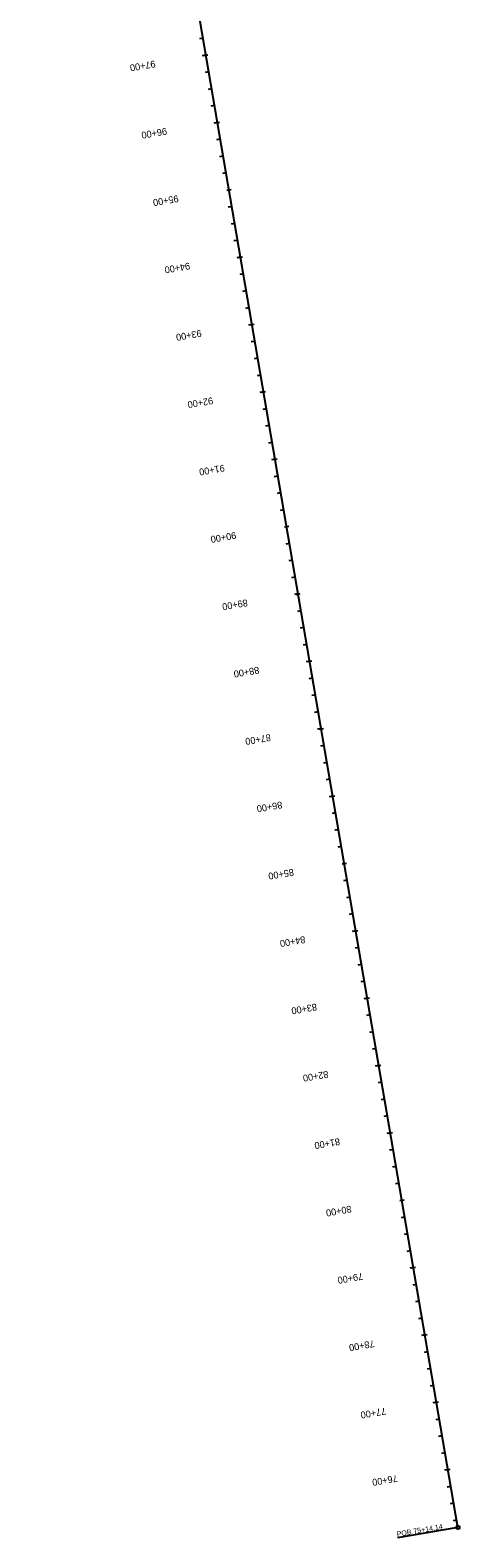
# Model space of a CAD drawing. Extents: x 11526371 to 11527168, y 9590726 to 9599509.
# Drawn here: x 11526540 to 11527168, y 9590726 to 9592932 of the extents above; entities that cross this region are included whole.
import ezdxf

# ---------------------------------------------------------------- set-up
doc = ezdxf.new("R2010")
doc.units = 0
for name, color, linetype in [('Alignment', 7, 'Continuous'), ('TextAlignment', 7, 'Continuous'), ('TextAlignmentLrg', 7, 'Continuous'), ('TextAlignmentSml', 7, 'Continuous')]:
    doc.layers.add(name, color=color, linetype=linetype)

msp = doc.modelspace()

# ---------------------------------------------------------------- linework, layer by layer
at = {"layer": 'Alignment'}
msp.add_line((11527165.7, 9590741), (11526539.8, 9594397.6), dxfattribs=at)
at = {"layer": 'TextAlignment'}
for p in [(11527165.7, 9590741), (11527077, 9590725.8)]:
    msp.add_line(p, (11527077, 9590725.8), dxfattribs=at)
msp.add_circle((11527165.7, 9590741), 2.67, dxfattribs=at)
at = {"layer": 'TextAlignmentLrg'}
for p, q in [((11526796.9, 9592895.5), (11526791.5, 9592894.6)), ((11526813.8, 9592796.9), (11526808.4, 9592796)), ((11526827.7, 9592697.8), (11526833.7, 9592698.9)), ((11526847.5, 9592599.8), (11526842.2, 9592598.9)), ((11526864.4, 9592501.2), (11526859, 9592500.3)), ((11526881.3, 9592402.7), (11526875.9, 9592401.7)), ((11526898.2, 9592304.1), (11526892.8, 9592303.2)), ((11526912, 9592205), (11526918, 9592206)), ((11526931.9, 9592107), (11526926.5, 9592106)), ((11526948.8, 9592008.4), (11526943.4, 9592007.5)), ((11526965.6, 9591909.8), (11526960.3, 9591908.9)), ((11526982.5, 9591811.3), (11526977.1, 9591810.3)), ((11526996.4, 9591712.2), (11527002.4, 9591713.2)), ((11527016.3, 9591614.1), (11527010.9, 9591613.2)), ((11527033.1, 9591515.6), (11527027.8, 9591514.6)), ((11527050, 9591417), (11527044.6, 9591416.1)), ((11527066.9, 9591318.4), (11527061.5, 9591317.5)), ((11527080.7, 9591219.3), (11527086.8, 9591220.4)), ((11527100.6, 9591121.3), (11527095.2, 9591120.4)), ((11527117.5, 9591022.7), (11527112.1, 9591021.8)), ((11527134.4, 9590924.2), (11527129, 9590923.2)), ((11527151.2, 9590825.6), (11527145.9, 9590824.7))]:
    msp.add_line(p, q, dxfattribs=at)
at = {"layer": 'TextAlignmentSml'}
for p, q in [((11526792.7, 9592920.1), (11526787.3, 9592919.2)), ((11526793.9, 9592895), (11526799.9, 9592896)), ((11526801.1, 9592870.9), (11526795.8, 9592869.9)), ((11526805.4, 9592846.2), (11526800, 9592845.3)), ((11526809.6, 9592821.6), (11526804.2, 9592820.6)), ((11526810.8, 9592796.4), (11526816.8, 9592797.4)), ((11526818, 9592772.3), (11526812.6, 9592771.4)), ((11526822.2, 9592747.6), (11526816.9, 9592746.7)), ((11526826.5, 9592723), (11526821.1, 9592722.1)), ((11526827.7, 9592697.8), (11526833.7, 9592698.9)), ((11526834.9, 9592673.7), (11526829.5, 9592672.8)), ((11526839.1, 9592649.1), (11526833.7, 9592648.2)), ((11526843.3, 9592624.4), (11526837.9, 9592623.5)), ((11526844.5, 9592599.3), (11526850.6, 9592600.3)), ((11526851.8, 9592575.2), (11526846.4, 9592574.2)), ((11526856, 9592550.5), (11526850.6, 9592549.6)), ((11526860.2, 9592525.9), (11526854.8, 9592524.9)), ((11526861.4, 9592500.7), (11526867.4, 9592501.7)), ((11526868.6, 9592476.6), (11526863.3, 9592475.7)), ((11526872.9, 9592451.9), (11526867.5, 9592451)), ((11526877.1, 9592427.3), (11526871.7, 9592426.4)), ((11526878.3, 9592402.1), (11526884.3, 9592403.2)), ((11526885.5, 9592378), (11526880.1, 9592377.1)), ((11526889.7, 9592353.4), (11526884.3, 9592352.5)), ((11526893.9, 9592328.7), (11526888.6, 9592327.8)), ((11526895.1, 9592303.6), (11526901.2, 9592304.6)), ((11526902.4, 9592279.5), (11526897, 9592278.5)), ((11526906.6, 9592254.8), (11526901.2, 9592253.9)), ((11526910.8, 9592230.2), (11526905.4, 9592229.2)), ((11526912, 9592205), (11526918, 9592206)), ((11526919.3, 9592180.9), (11526913.9, 9592180)), ((11526923.5, 9592156.2), (11526918.1, 9592155.3)), ((11526927.7, 9592131.6), (11526922.3, 9592130.7)), ((11526928.9, 9592106.4), (11526934.9, 9592107.5)), ((11526936.1, 9592082.3), (11526930.7, 9592081.4)), ((11526940.3, 9592057.7), (11526935, 9592056.8)), ((11526944.6, 9592033), (11526939.2, 9592032.1)), ((11526945.8, 9592007.9), (11526951.8, 9592008.9)), ((11526953, 9591983.8), (11526947.6, 9591982.8)), ((11526957.2, 9591959.1), (11526951.8, 9591958.2)), ((11526961.4, 9591934.5), (11526956, 9591933.5)), ((11526962.6, 9591909.3), (11526968.7, 9591910.3)), ((11526969.9, 9591885.2), (11526964.5, 9591884.3)), ((11526974.1, 9591860.5), (11526968.7, 9591859.6)), ((11526978.3, 9591835.9), (11526972.9, 9591835)), ((11526979.5, 9591810.7), (11526985.5, 9591811.8)), ((11526986.7, 9591786.6), (11526981.4, 9591785.7)), ((11526991, 9591762), (11526985.6, 9591761.1)), ((11526995.2, 9591737.3), (11526989.8, 9591736.4)), ((11526996.4, 9591712.2), (11527002.4, 9591713.2)), ((11527003.6, 9591688.1), (11526998.2, 9591687.1)), ((11527007.8, 9591663.4), (11527002.4, 9591662.5)), ((11527012, 9591638.8), (11527006.7, 9591637.8)), ((11527013.2, 9591613.6), (11527019.3, 9591614.6)), ((11527020.5, 9591589.5), (11527015.1, 9591588.6)), ((11527024.7, 9591564.8), (11527019.3, 9591563.9)), ((11527028.9, 9591540.2), (11527023.5, 9591539.3)), ((11527030.1, 9591515), (11527036.2, 9591516.1)), ((11527037.4, 9591490.9), (11527032, 9591490)), ((11527041.6, 9591466.3), (11527036.2, 9591465.4)), ((11527045.8, 9591441.6), (11527040.4, 9591440.7)), ((11527047, 9591416.5), (11527053, 9591417.5)), ((11527054.2, 9591392.4), (11527048.8, 9591391.4)), ((11527058.4, 9591367.7), (11527053.1, 9591366.8)), ((11527062.7, 9591343.1), (11527057.3, 9591342.1)), ((11527063.9, 9591317.9), (11527069.9, 9591318.9)), ((11527071.1, 9591293.8), (11527065.7, 9591292.9)), ((11527075.3, 9591269.1), (11527069.9, 9591268.2)), ((11527079.5, 9591244.5), (11527074.2, 9591243.6)), ((11527080.7, 9591219.3), (11527086.8, 9591220.4)), ((11527088, 9591195.2), (11527082.6, 9591194.3)), ((11527092.2, 9591170.6), (11527086.8, 9591169.7)), ((11527096.4, 9591145.9), (11527091, 9591145)), ((11527097.6, 9591120.8), (11527103.6, 9591121.8)), ((11527104.8, 9591096.7), (11527099.5, 9591095.7)), ((11527109.1, 9591072), (11527103.7, 9591071.1)), ((11527113.3, 9591047.4), (11527107.9, 9591046.5)), ((11527114.5, 9591022.2), (11527120.5, 9591023.2)), ((11527121.7, 9590998.1), (11527116.3, 9590997.2)), ((11527125.9, 9590973.4), (11527120.5, 9590972.5)), ((11527130.1, 9590948.8), (11527124.8, 9590947.9)), ((11527131.3, 9590923.6), (11527137.4, 9590924.7)), ((11527138.6, 9590899.5), (11527133.2, 9590898.6)), ((11527142.8, 9590874.9), (11527137.4, 9590874)), ((11527147, 9590850.2), (11527141.6, 9590849.3)), ((11527148.2, 9590825.1), (11527154.3, 9590826.1)), ((11527155.5, 9590801), (11527150.1, 9590800)), ((11527159.7, 9590776.3), (11527154.3, 9590775.4)), ((11527163.9, 9590751.7), (11527158.5, 9590750.8))]:
    msp.add_line(p, q, dxfattribs=at)

# ---------------------------------------------------------------- texts
at = {"layer": 'TextAlignment'}
for s, p in [('POB ', (11527076.7, 9590727.4)), ('75+14.14', (11527101, 9590731.6))]:
    msp.add_text(s, height=7.5, rotation=9.7133, dxfattribs=at).set_placement(p)
at = {"layer": 'TextAlignmentLrg'}
for s, p in [('95+00', (11526755.9, 9592690.6)), ('90+00', (11526840.3, 9592197.8)), ('85+00', (11526924.6, 9591705)), ('80+00', (11527009, 9591212.1))]:
    msp.add_text(s, height=10.02, rotation=189.7133, dxfattribs=at).set_placement(p)
at = {"layer": 'TextAlignmentSml'}
for s, p in [('97+00', (11526722.2, 9592887.8)), ('96+00', (11526739, 9592789.2)), ('95+00', (11526755.9, 9592690.6)), ('94+00', (11526772.8, 9592592.1)), ('93+00', (11526789.6, 9592493.5)), ('92+00', (11526806.5, 9592394.9)), ('91+00', (11526823.4, 9592296.4)), ('90+00', (11526840.3, 9592197.8)), ('89+00', (11526857.1, 9592099.2)), ('88+00', (11526874, 9592000.7)), ('87+00', (11526890.9, 9591902.1)), ('86+00', (11526907.7, 9591803.5)), ('85+00', (11526924.6, 9591705)), ('84+00', (11526941.5, 9591606.4)), ('83+00', (11526958.4, 9591507.8)), ('82+00', (11526975.2, 9591409.3)), ('81+00', (11526992.1, 9591310.7)), ('80+00', (11527009, 9591212.1)), ('79+00', (11527025.9, 9591113.6)), ('78+00', (11527042.7, 9591015)), ('77+00', (11527059.6, 9590916.4)), ('76+00', (11527076.5, 9590817.9))]:
    msp.add_text(s, height=10.02, rotation=189.7133, dxfattribs=at).set_placement(p)

doc.saveas('drawing.dxf')
